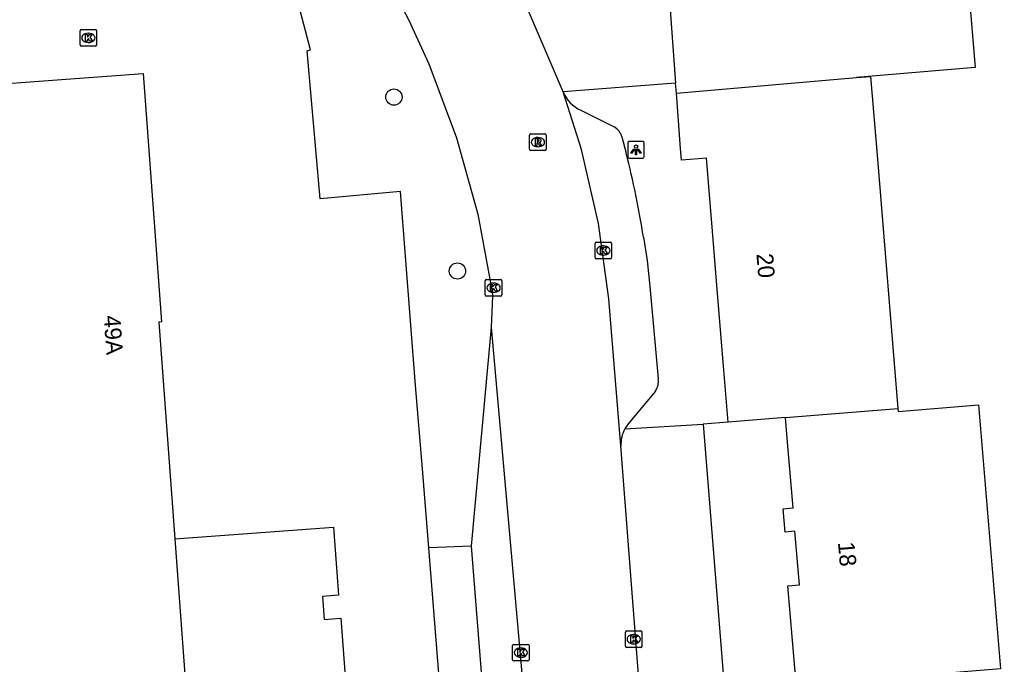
# Model space of a CAD drawing. Extents: x 157793 to 159380, y 380882 to 382313.
# Drawn here: x 158110.5 to 158169.5, y 381260.1 to 381298.9 of the extents above; entities that cross this region are included whole.
import ezdxf

# ---------------------------------------------------------------- set-up
doc = ezdxf.new("R2010")
doc.units = 0
for name, color, linetype in [('IMGEO_Boom', 7, 'Continuous'), ('IMGEO_Kolk', 7, 'Continuous'), ('IMGEO_Lichtpunt', 7, 'Continuous'), ('IMGEO_OVBaan_gesloten', 7, 'Continuous'), ('IMGEO_Pand', 7, 'Continuous'), ('IMGEO_Pand_nummerreeks', 7, 'Continuous'), ('IMGEO_Rijbaan_lokaal_gesloten', 7, 'Continuous'), ('IMGEO_Rioolput', 7, 'Continuous'), ('IMGEO_Voetpad_open', 7, 'Continuous')]:
    doc.layers.add(name, color=color, linetype=linetype)

msp = doc.modelspace()

# ---------------------------------------------------------------- linework, layer by layer
at = {"layer": 'IMGEO_Boom'}
for centre in [(158133.019, 381294.285), (158136.842, 381283.812)]:
    msp.add_circle(centre, 0.489, dxfattribs=at)
at = {"layer": 'IMGEO_Kolk'}
for p, q in [((158114.139, 381297.424), (158114.139, 381298.276)), ((158114.214, 381298.35), (158115.066, 381298.35)), ((158115.14, 381298.276), (158115.14, 381297.424)), ((158114.627, 381298.13), (158114.652, 381298.13)), ((158115.066, 381297.35), (158114.214, 381297.35)), ((158114.65, 381297.57), (158114.625, 381297.57)), ((158145.118, 381284.623), (158145.118, 381285.475)), ((158145.193, 381285.549), (158146.045, 381285.549)), ((158145.606, 381285.329), (158145.631, 381285.329)), ((158146.119, 381285.475), (158146.119, 381284.623)), ((158145.629, 381284.769), (158145.604, 381284.769)), ((158146.045, 381284.549), (158145.193, 381284.549)), ((158138.514, 381282.377), (158138.514, 381283.229)), ((158138.589, 381283.303), (158139.441, 381283.303)), ((158139.002, 381283.083), (158139.027, 381283.083)), ((158139.515, 381283.229), (158139.515, 381282.377)), ((158139.441, 381282.303), (158138.589, 381282.303)), ((158139.025, 381282.523), (158139, 381282.523)), ((158146.943, 381261.22), (158146.943, 381262.072)), ((158147.018, 381262.146), (158147.87, 381262.146)), ((158147.431, 381261.926), (158147.456, 381261.926)), ((158147.944, 381262.072), (158147.944, 381261.22)), ((158140.156, 381260.412), (158140.156, 381261.264)), ((158140.231, 381261.338), (158141.083, 381261.338)), ((158140.644, 381261.118), (158140.669, 381261.118)), ((158141.157, 381261.264), (158141.157, 381260.412)), ((158147.87, 381261.146), (158147.018, 381261.146)), ((158147.454, 381261.366), (158147.429, 381261.366)), ((158140.667, 381260.558), (158140.642, 381260.558)), ((158141.083, 381260.338), (158140.231, 381260.338))]:
    msp.add_line(p, q, dxfattribs=at)
for points in [[(158114.139, 381297.424), (158114.139, 381298.276)], [(158114.214, 381298.35), (158115.066, 381298.35)], [(158115.14, 381298.276), (158115.14, 381297.424)], [(158114.46, 381298.05), (158114.583, 381298.05), (158114.583, 381297.899), (158114.713, 381298.05), (158114.877, 381298.05), (158114.731, 381297.899), (158114.884, 381297.65), (158114.732, 381297.65), (158114.647, 381297.814), (158114.583, 381297.747), (158114.583, 381297.65), (158114.46, 381297.65), (158114.46, 381298.05)], [(158115.066, 381297.35), (158114.214, 381297.35)], [(158145.118, 381284.623), (158145.118, 381285.475)], [(158145.193, 381285.549), (158146.045, 381285.549)], [(158145.439, 381285.249), (158145.562, 381285.249), (158145.562, 381285.098), (158145.692, 381285.249), (158145.856, 381285.249), (158145.71, 381285.098), (158145.863, 381284.849), (158145.711, 381284.849), (158145.626, 381285.013), (158145.562, 381284.946), (158145.562, 381284.849), (158145.439, 381284.849), (158145.439, 381285.249)], [(158146.119, 381285.475), (158146.119, 381284.623)], [(158146.045, 381284.549), (158145.193, 381284.549)], [(158138.514, 381282.377), (158138.514, 381283.229)], [(158138.589, 381283.303), (158139.441, 381283.303)], [(158138.835, 381283.003), (158138.958, 381283.003), (158138.958, 381282.852), (158139.088, 381283.003), (158139.252, 381283.003), (158139.106, 381282.852), (158139.259, 381282.603), (158139.107, 381282.603), (158139.022, 381282.767), (158138.958, 381282.7), (158138.958, 381282.603), (158138.835, 381282.603), (158138.835, 381283.003)], [(158139.515, 381283.229), (158139.515, 381282.377)], [(158139.441, 381282.303), (158138.589, 381282.303)], [(158146.943, 381261.22), (158146.943, 381262.072)], [(158147.018, 381262.146), (158147.87, 381262.146)], [(158147.264, 381261.846), (158147.387, 381261.846), (158147.387, 381261.695), (158147.517, 381261.846), (158147.681, 381261.846), (158147.535, 381261.695), (158147.688, 381261.446), (158147.536, 381261.446), (158147.451, 381261.61), (158147.387, 381261.543), (158147.387, 381261.446), (158147.264, 381261.446), (158147.264, 381261.846)], [(158147.944, 381262.072), (158147.944, 381261.22)], [(158140.156, 381260.412), (158140.156, 381261.264)], [(158140.231, 381261.338), (158141.083, 381261.338)], [(158140.477, 381261.038), (158140.6, 381261.038), (158140.6, 381260.887), (158140.73, 381261.038), (158140.894, 381261.038), (158140.748, 381260.887), (158140.901, 381260.638), (158140.749, 381260.638), (158140.664, 381260.802), (158140.6, 381260.735), (158140.6, 381260.638), (158140.477, 381260.638), (158140.477, 381261.038)], [(158141.157, 381261.264), (158141.157, 381260.412)], [(158147.87, 381261.146), (158147.018, 381261.146)], [(158141.083, 381260.338), (158140.231, 381260.338)]]:
    msp.add_lwpolyline(points, dxfattribs=at)
for centre, start, end in [((158114.216, 381298.274), 91.55205, 178.44795), ((158114.216, 381298.274), 91.55205, 178.44795), ((158115.064, 381298.274), 1.55205, 88.44795), ((158115.064, 381298.274), 1.55205, 88.44795), ((158114.216, 381297.426), 181.55205, 268.44795), ((158114.216, 381297.426), 181.55205, 268.44795), ((158115.064, 381297.426), 271.55205, 358.44795), ((158115.064, 381297.426), 271.55205, 358.44795), ((158145.195, 381285.473), 91.55205, 178.44795), ((158145.195, 381285.473), 91.55205, 178.44795), ((158146.043, 381285.473), 1.55205, 88.44795), ((158146.043, 381285.473), 1.55205, 88.44795), ((158145.195, 381284.625), 181.55205, 268.44795), ((158145.195, 381284.625), 181.55205, 268.44795), ((158146.043, 381284.625), 271.55205, 358.44795), ((158146.043, 381284.625), 271.55205, 358.44795), ((158138.591, 381283.227), 91.55205, 178.44795), ((158138.591, 381283.227), 91.55205, 178.44795), ((158139.439, 381283.227), 1.55205, 88.44795), ((158139.439, 381283.227), 1.55205, 88.44795), ((158138.591, 381282.379), 181.55205, 268.44795), ((158138.591, 381282.379), 181.55205, 268.44795), ((158139.439, 381282.379), 271.55205, 358.44795), ((158139.439, 381282.379), 271.55205, 358.44795), ((158147.02, 381262.07), 91.55205, 178.44795), ((158147.02, 381262.07), 91.55205, 178.44795), ((158147.868, 381262.07), 1.55205, 88.44795), ((158147.868, 381262.07), 1.55205, 88.44795), ((158140.233, 381261.262), 91.55205, 178.44795), ((158140.233, 381261.262), 91.55205, 178.44795), ((158141.081, 381261.262), 1.55205, 88.44795), ((158141.081, 381261.262), 1.55205, 88.44795), ((158147.02, 381261.222), 181.55205, 268.44795), ((158147.02, 381261.222), 181.55205, 268.44795), ((158147.868, 381261.222), 271.55205, 358.44795), ((158147.868, 381261.222), 271.55205, 358.44795), ((158140.233, 381260.414), 181.55205, 268.44795), ((158140.233, 381260.414), 181.55205, 268.44795), ((158141.081, 381260.414), 271.55205, 358.44795), ((158141.081, 381260.414), 271.55205, 358.44795)]:
    msp.add_arc(centre, 0.0765, start, end, dxfattribs=at)
for centre, major_axis, ratio, start_param, end_param in [((158114.626, 381297.85), (-0.387, 0.002), 0.722429, 4.712389, 7.853982), ((158114.651, 381297.85), (-0.39, 0.002), 0.717154, 1.570796, 4.712389), ((158145.605, 381285.049), (-0.387, 0.002), 0.722429, 4.712389, 7.853982), ((158145.63, 381285.049), (-0.39, 0.002), 0.717154, 1.570796, 4.712389), ((158139.001, 381282.803), (-0.387, 0.002), 0.722429, 4.712389, 7.853982), ((158139.026, 381282.803), (-0.39, 0.002), 0.717154, 1.570796, 4.712389), ((158147.43, 381261.646), (-0.387, 0.002), 0.722429, 4.712389, 7.853982), ((158147.455, 381261.646), (-0.39, 0.002), 0.717154, 1.570796, 4.712389), ((158140.643, 381260.838), (-0.387, 0.002), 0.722429, 4.712389, 7.853982), ((158140.668, 381260.838), (-0.39, 0.002), 0.717154, 1.570796, 4.712389)]:
    msp.add_ellipse(centre, major_axis=major_axis, ratio=ratio, start_param=start_param, end_param=end_param, dxfattribs=at)
at = {"layer": 'IMGEO_Lichtpunt'}
for p, q in [((158147.087, 381291.509), (158147.087, 381290.702)), ((158147.087, 381291.509), (158147.087, 381290.702)), ((158147.989, 381291.604), (158147.181, 381291.604)), ((158147.989, 381291.604), (158147.181, 381291.604)), ((158148.083, 381290.702), (158148.083, 381291.509)), ((158148.083, 381290.702), (158148.083, 381291.509)), ((158147.181, 381290.608), (158147.989, 381290.608)), ((158147.181, 381290.608), (158147.989, 381290.608))]:
    msp.add_line(p, q, dxfattribs=at)
for points in [[(158147.461, 381291.173), (158147.5, 381291.145), (158147.312, 381290.883), (158147.274, 381290.91), (158147.461, 381291.173)], [(158147.563, 381291.125), (158147.61, 381291.125), (158147.61, 381290.803), (158147.563, 381290.803), (158147.563, 381291.125)], [(158147.673, 381291.145), (158147.711, 381291.172), (158147.898, 381290.91), (158147.859, 381290.882), (158147.673, 381291.145)]]:
    msp.add_lwpolyline(points, dxfattribs=at)
msp.add_circle((158147.586, 381291.307), 0.0994, dxfattribs=at)
for centre, start, end in [((158147.181, 381291.509), 90, 180), ((158147.181, 381291.509), 90, 180), ((158147.989, 381291.509), 0, 90), ((158147.989, 381291.509), 0, 90), ((158147.181, 381290.702), 180, 270), ((158147.181, 381290.702), 180, 270), ((158147.989, 381290.702), 270, 0), ((158147.989, 381290.702), 270, 360)]:
    msp.add_arc(centre, 0.0946, start, end, dxfattribs=at)
at = {"layer": 'IMGEO_OVBaan_gesloten'}
for points in [[(158138.872, 381280.436), (158137.665, 381267.241)], [(158138.872, 381280.436), (158142.335, 381241.215)], [(158137.665, 381267.241), (158139.011, 381250.296)]]:
    msp.add_lwpolyline(points, dxfattribs=at)
at = {"layer": 'IMGEO_Pand'}
for points in [[(158166.317, 381315.953), (158167.979, 381296.063), (158160.857, 381295.455)], [(158148.612, 381312.832), (158148.658, 381312.275), (158149.209, 381305.365), (158149.969, 381295.114)], [(158110.766, 381249.754), (158090.893, 381248.222), (158090.756, 381250), (158087.398, 381293.448), (158117.931, 381295.704), (158119.036, 381280.745), (158118.876, 381280.733), (158119.84, 381267.681)], [(158150.013, 381294.53), (158159.691, 381295.356), (158160.857, 381295.455)], [(158160.857, 381295.455), (158161.69, 381295.523), (158162.102, 381290.54), (158163.343, 381275.531)], [(158150.013, 381294.53), (158149.969, 381295.114)], [(158153.133, 381274.721), (158152.855, 381278.087), (158152.431, 381283.212), (158152.182, 381286.221), (158151.82, 381290.603), (158150.313, 381290.478), (158150.26, 381291.187), (158150.013, 381294.53)], [(158163.343, 381275.531), (158163.357, 381275.358), (158168.188, 381275.758), (158169.503, 381259.859), (158162.895, 381259.313), (158157.911, 381258.901), (158157.957, 381258.343), (158157.27, 381258.287), (158156.726, 381264.864), (158157.414, 381264.921), (158157.147, 381268.15), (158156.548, 381268.101), (158156.433, 381269.506), (158157.03, 381269.555), (158156.705, 381273.503), (158156.623, 381274.491), (158156.582, 381274.995)], [(158156.582, 381274.995), (158163.343, 381275.531)], [(158156.582, 381274.995), (158153.133, 381274.721)], [(158119.84, 381267.681), (158129.392, 381268.386), (158129.694, 381264.293), (158128.73, 381264.222), (158128.832, 381262.833), (158129.832, 381262.907), (158130.795, 381250), (158130.974, 381247.604), (158128.29, 381247.398), (158128.714, 381241.897), (158120.298, 381241.248), (158111.474, 381240.568), (158110.766, 381249.754)], [(158119.84, 381267.681), (158121.105, 381250.551), (158113.957, 381250), (158110.766, 381249.754)]]:
    msp.add_lwpolyline(points, dxfattribs=at)
at = {"layer": 'IMGEO_Rijbaan_lokaal_gesloten'}
for points in [[(158063.323, 381491.963), (158084.358, 381449.773), (158097, 381424.252), (158097.468, 381423.282), (158100.308, 381416.538), (158102.534, 381409.567), (158104.129, 381402.425), (158105.079, 381395.169), (158108.678, 381349.094), (158108.99, 381346.367), (158109.545, 381343.679), (158109.885, 381342.445), (158111.071, 381338.314), (158112.621, 381334.306), (158114.523, 381330.452), (158114.85, 381329.868), (158129.631, 381306.832), (158130.692, 381305.062), (158133.891, 381298.949)], [(158143.195, 381294.604), (158139.003, 381304.419), (158134.841, 381311.603), (158134.72, 381311.792)], [(158133.891, 381298.949), (158135.117, 381296.291), (158136.795, 381291.831), (158138.068, 381287.238), (158138.925, 381282.55), (158138.944, 381282.307), (158138.872, 381280.436)], [(158146.678, 381273.28), (158145.948, 381282.137), (158145.324, 381286.667), (158144.297, 381291.124), (158143.195, 381294.604)], [(158148.273, 381253.043), (158148.225, 381253.262), (158146.678, 381273.28)]]:
    msp.add_lwpolyline(points, dxfattribs=at)
at = {"layer": 'IMGEO_Rioolput'}
for p, q in [((158141.182, 381291.145), (158141.182, 381291.997)), ((158141.257, 381292.071), (158142.109, 381292.071)), ((158141.67, 381291.851), (158141.695, 381291.851)), ((158142.183, 381291.997), (158142.183, 381291.145)), ((158141.693, 381291.291), (158141.668, 381291.291)), ((158142.109, 381291.071), (158141.257, 381291.071))]:
    msp.add_line(p, q, dxfattribs=at)
for points in [[(158141.182, 381291.145), (158141.182, 381291.997)], [(158141.257, 381292.071), (158142.109, 381292.071)], [(158141.771, 381291.769), (158141.519, 381291.771), (158141.519, 381291.371)], [(158141.697, 381291.69), (158141.643, 381291.69), (158141.643, 381291.609)], [(158142.183, 381291.997), (158142.183, 381291.145)], [(158141.519, 381291.371), (158141.643, 381291.371), (158141.643, 381291.533), (158141.654, 381291.533)], [(158141.643, 381291.609), (158141.695, 381291.609)], [(158141.701, 381291.504), (158141.772, 381291.371), (158141.912, 381291.371), (158141.847, 381291.497)], [(158142.109, 381291.071), (158141.257, 381291.071)]]:
    msp.add_lwpolyline(points, dxfattribs=at)
for centre, radius, start, end in [((158141.259, 381291.995), 0.0765, 91.55205, 178.44795), ((158141.259, 381291.995), 0.0765, 91.55205, 178.44795), ((158141.703, 381291.594), 0.0964, 77.00612, 93.18647), ((158141.717, 381291.651), 0.0378, 276.66336, 79.67722), ((158141.77, 381291.659), 0.109, 350.36119, 89.41601), ((158142.107, 381291.995), 0.0765, 1.55205, 88.44795), ((158142.107, 381291.995), 0.0765, 1.55205, 88.44795), ((158141.259, 381291.147), 0.0765, 181.55205, 268.44795), ((158141.259, 381291.147), 0.0765, 181.55205, 268.44795), ((158141.653, 381291.48), 0.0533, 26.02933, 88.69889), ((158141.679, 381291.798), 0.19, 274.7715, 282.96867), ((158141.768, 381291.659), 0.112, 277.58423, 350.98172), ((158141.752, 381291.444), 0.108, 29.51342, 73.79051), ((158142.107, 381291.147), 0.0765, 271.55205, 358.44795), ((158142.107, 381291.147), 0.0765, 271.55205, 358.44795)]:
    msp.add_arc(centre, radius, start, end, dxfattribs=at)
for centre, major_axis, ratio, start_param, end_param in [((158141.669, 381291.571), (-0.387, 0.002), 0.722429, 4.712389, 7.853982), ((158141.694, 381291.571), (-0.39, 0.002), 0.717154, 1.570796, 4.712389)]:
    msp.add_ellipse(centre, major_axis=major_axis, ratio=ratio, start_param=start_param, end_param=end_param, dxfattribs=at)
at = {"layer": 'IMGEO_Voetpad_open'}
for points in [[(158135.122, 381267.156), (158134.745, 381271.897), (158134.324, 381276.911), (158133.427, 381288.599), (158128.577, 381288.152), (158127.803, 381297.075), (158127.997, 381297.125), (158126.787, 381301.809), (158126.593, 381301.759), (158125.087, 381304.314), (158119.05, 381313.79), (158110.244, 381327.475)], [(158149.969, 381295.114), (158143.195, 381294.604)], [(158144.256, 381293.495), (158146.277, 381292.498)], [(158146.74, 381291.9), (158146.998, 381290.908)], [(158148.033, 381285.845), (158148.247, 381284.452), (158148.416, 381282.877), (158148.881, 381277.784), (158148.925, 381277.317)], [(158148.754, 381276.589), (158147.113, 381274.618), (158146.913, 381274.316)], [(158146.913, 381274.316), (158151.631, 381274.599)], [(158153.133, 381274.721), (158151.631, 381274.599)], [(158151.631, 381274.599), (158153.242, 381254.297), (158153.62, 381250), (158153.955, 381246.186), (158154.327, 381240.281)], [(158137.665, 381267.241), (158135.122, 381267.156)], [(158136.484, 381250), (158135.122, 381267.156)]]:
    msp.add_lwpolyline(points, dxfattribs=at)
for centre, radius, start, end in [((158145.126, 381295.389), 2.085, 202.13157, 245.3341), ((158145.686, 381291.562), 1.107, 17.76782, 57.72965), ((158088.825, 381276.379), 59.96, 9.08365, 14.02328), ((158147.936, 381277.165), 1, 324.82885, 8.73399), ((158148.69, 381273.368), 2.014, 151.92516, 182.51413)]:
    msp.add_arc(centre, radius, start, end, dxfattribs=at)

# ---------------------------------------------------------------- texts
at = {"layer": 'IMGEO_Pand_nummerreeks'}
for s, rotation, p in [('20', 274.72669, (158154.825, 381284.839)), ('49A', 274.22411, (158115.559, 381281.112)), ('18', 274.72669, (158159.732, 381267.473))]:
    msp.add_text(s, height=1, rotation=rotation, dxfattribs=at).set_placement(p)

doc.saveas('drawing.dxf')
